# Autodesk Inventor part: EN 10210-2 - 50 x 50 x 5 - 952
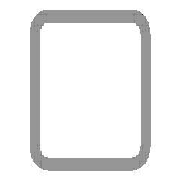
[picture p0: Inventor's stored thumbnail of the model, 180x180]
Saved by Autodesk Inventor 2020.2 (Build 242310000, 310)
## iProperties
IsCustomPart: 1
_CCFamilyMember: 16
_CCFamilyDisplayName: DIN EN 10210-2 (USAS B17.1 quadratisch) - Rohrleitung — In Klammern angegebene Größen wurden aufgehoben
_FrameMemberDoc: Frame Member File
_Version: 15.0.0
_GetPNFromCC: 1
Created: 2019-10
Part Number: EN 10210-2 - 50 x 50 x 5 - 952
Material: Stahl, weich
Description: Rohrleitung
Document SubType Name: Modeling
Standard: DIN
Designer: lutzd
Standard Revision: 2006-07
Standards Organization: DIN
Language: de-DE
Size Designation: 50 x 50 x 5
Categories: <MemberInstance><Categories><Category DisplayName="Profile" InternalName="089c4875-fa83-4c05-b084-43b9cc11f5ed" Mnemonic="GRDR"><CategoryParameter DisplayName="
Stock Number: 50 x 50 x 5
Mass: 6496.05 g
Surface Area: 3238.8 cm^2
Volume: 827.522 cm^3
Density: 7.85 g/cm^3
Appearance: Semi-Polished(8)
G_L: 952,000 mm
G_W: 50,000 mm
G_H: 50,000 mm
Dimensions: 50x50x952 mm
Mass: 6,496 kg
DocNumber: ADSK-014282
Folder: .
+0ED5C9ED-8ADB-457E-A39F-7B09B21A4AF6+SCHNITTDETAIL1: Schnittwinkel 90,00 grd
VLT_Material: Stahl, weich
Title: Profil-Bauteil
Author: lutzd
Revision Number: -
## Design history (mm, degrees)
node "Startebene"
node "Endebene"
sketch "Skizze"
  geometry: L1 (-25, -17.5)-(-25, 17.5); L2 (-17.5, 25)-(17.5, 25); L3 (25, 17.5)-(25, -17.5); L4 (17.5, -25)-(-17.5, -25); L5 (-15, 20)-(15, 20); L6 (20, 15)-(20, -15); L7 (15, -20)-(-15, -20); L8 (-20, -15)-(-20, 15); L9 (0, 37.175)-(0, -37.175) reference; L10 (-37.175, 0)-(37.175, 0) reference; A1 r 7.5 centre (-17.5, -17.5) between (-25, -17.5) and (-17.5, -25); A2 r 7.5 centre (-17.5, 17.5) between (-17.5, 25) and (-25, 17.5); A3 r 7.5 centre (17.5, 17.5) between (25, 17.5) and (17.5, 25); A4 r 7.5 centre (17.5, -17.5) between (17.5, -25) and (25, -17.5); A5 r 5 centre (-15, -15) between (-20, -15) and (-15, -20); A6 r 5 centre (-15, 15) between (-15, 20) and (-20, 15); A7 r 5 centre (15, 15) between (20, 15) and (15, 20); A8 r 5 centre (15, -15) between (15, -20) and (20, -15)
  constraints: 16 end point, 16 point on circle, 16 tangent, 8 centre point, 6 equal radius, 4 parallel, 2 perpendicular, 2 other
  dimensions: "d7" = 7.5 radius of A1 (= G_IR); "d10" = 50 distance between parallel lines of L2 L4 (= G_H); "d11" = 50 distance between parallel lines of L1 L3 (= G_W); "d12" = 5 distance between parallel lines of L3 L6 (= G_T); "d15" = 25 distance between parallel lines of L2 L10 (= 0.5 x d10); "d16" = 25 distance between parallel lines of L9 L3 (= 0.5 x d11); "d19" = 5 radius of A5 (= G_T); "d20" = 5 distance between parallel lines of L4 L7 (= G_T)
extrude "Körper" new body sketch "Skizze" stored distance "d3" = 952 (= G_L); taper "d4" = 0 deg
node "Driven Length"
  sketch "Sketch3"
    geometry: L1 (0, 0)-(10, 0) reference
    constraints: 2 end point, 1 horizontal
  workplane "Work Plane3"
  sketch "Sketch4"
    geometry: L1 (-2, -25)-(12, -25) reference; L2 (-2, 927)-(12, 927) reference
    dimensions: "d18" = 952 distance between parallel lines of L1 L2 (derived)
workplane "Arbeitsebene4"
feature "Trennen1"
sketch "Skizze5"
  geometry: L1 (952, -35)-(952, 0) reference; L2 (952, -17.5)-(494.75, -17.5); 4 further points
  constraints: 4 end point, 2 point on line, 1 coincident, 1 horizontal, 1 midpoint, 1 vertical, 2 other
  dimensions: "d21" = 304.75 distance from line of L1 point (647.25, -17.5); "d22" = 152.5 distance of point (494.75, -17.5) point (647.25, -17.5); "d23" = 76.25 distance of point (494.75, -17.5) point (571, -17.5) (= 0.5 x d22)
hole "Bohrung1" sketch "Skizze5" at (647.25, -17.5), (571, -17.5), (494.75, -17.5) diameter "d24" = 12; stored, may be unused: countersink angle "d28" = 90 deg, drill point angle "d30" = 118 deg; dims "d25" = 6, "d26" = 4, "d27" = 2, "d29" = 8
sketch "Skizze6"
  geometry: L1 (35, 0)-(0, 0) reference; L2 (17.5, 0)-(17.5, 418.25); 3 further points
  constraints: 2 end point, 1 coincident, 1 midpoint, 1 point on line, 1 vertical
  dimensions: "d31" = 21.25 distance from line of L1 point (17.5, 21.25); "d32" = 397 distance of point (17.5, 418.25) point (17.5, 21.25)
hole "Bohrung2" sketch "Skizze6" at (17.5, 418.25), (17.5, 21.25) diameter "d33" = 6.647; stored, may be unused: countersink angle "d37" = 90 deg, drill point angle "d39" = 118 deg; dims "d34" = 16, "d35" = 4, "d36" = 2, "d38" = 8
body "Solid1"
other parameters: "G_W" = 50 [user parameter; used in 1 equation term], "G_H" = 50 [user parameter; used in 1 equation term], "G_T" = 5 [user parameter; used in 3 equation terms], "G_IR" = 7.5 [user parameter; used in 1 equation term], "G_L" = 952 (= d18) [user parameter; used in 1 equation term], "G_OFFSET_START" = 25 [user parameter; used in 1 equation term], "G_OFFSET_END" = 0 [user parameter; used in 1 equation term], "d13" = -25 (= -G_OFFSET_START), "d14" = 927 (= G_OFFSET_END + B_L), "B_L" = 927 [user parameter; used in 1 equation term], "d17" = 90 deg
